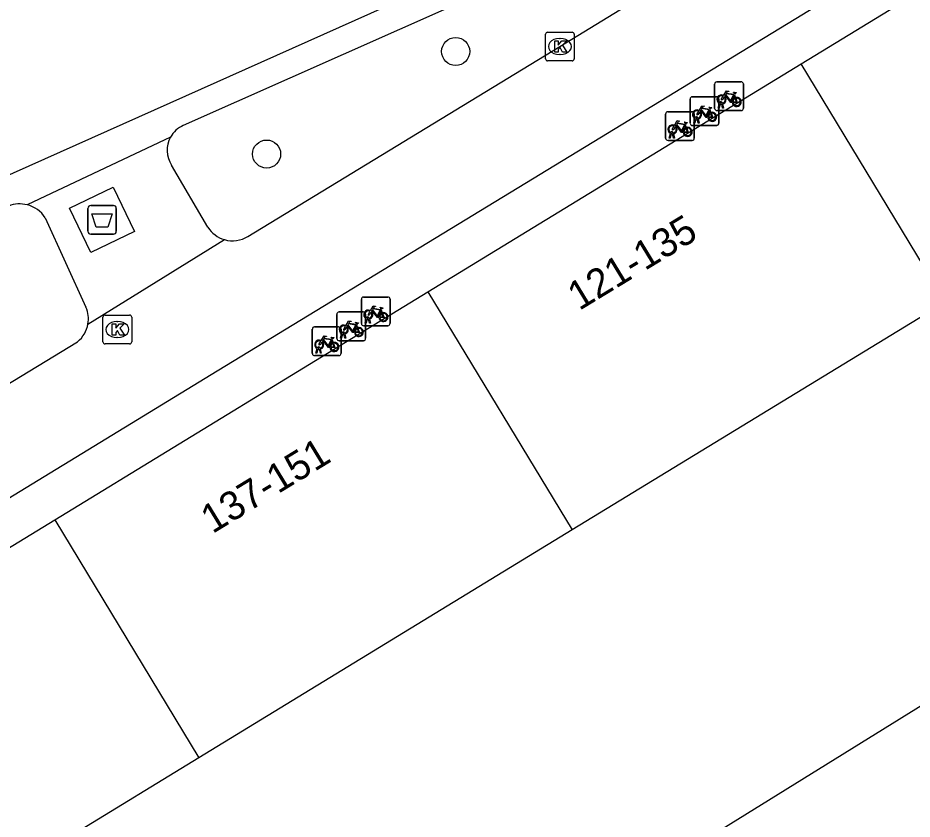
# Model space of a CAD drawing. Extents: x 159888 to 160757, y 384031 to 384746.
# Drawn here: x 160130.45 to 160161.59, y 384604.42 to 384632.33 of the extents above; entities that cross this region are included whole.
import ezdxf

# ---------------------------------------------------------------- set-up
doc = ezdxf.new("R2010")
doc.units = 0
for name, color, linetype in [('IMGEO_Afval_apart_plaats', 7, 'Continuous'), ('IMGEO_Boom', 7, 'Continuous'), ('IMGEO_Fietsenrek', 7, 'Continuous'), ('IMGEO_Groenvoorziening', 7, 'Continuous'), ('IMGEO_Kolk', 7, 'Continuous'), ('IMGEO_Pand', 7, 'Continuous'), ('IMGEO_Pand_nummerreeks', 7, 'Continuous'), ('IMGEO_Rijbaan_lokaal_open', 7, 'Continuous'), ('IMGEO_Voetpad_gesloten', 7, 'Continuous'), ('IMGEO_Voetpad_open', 7, 'Continuous')]:
    doc.layers.add(name, color=color, linetype=linetype)

msp = doc.modelspace()

# ---------------------------------------------------------------- linework, layer by layer
at = {"layer": 'IMGEO_Afval_apart_plaats'}
for p, q in [((160132.989, 384625.793), (160133.779, 384625.793)), ((160133.779, 384625.793), (160132.989, 384625.793)), ((160132.889, 384624.893), (160132.889, 384625.693)), ((160132.889, 384625.693), (160132.889, 384624.893)), ((160133.879, 384625.693), (160133.879, 384624.893)), ((160133.879, 384624.893), (160133.879, 384625.693)), ((160133.779, 384624.793), (160132.989, 384624.793)), ((160132.989, 384624.793), (160133.779, 384624.793))]:
    msp.add_line(p, q, dxfattribs=at)
msp.add_lwpolyline([(160133.032, 384625.507), (160133.736, 384625.507), (160133.587, 384625.037), (160133.181, 384625.037), (160133.032, 384625.507)], dxfattribs=at)
for centre, start, end in [((160132.989, 384625.693), 90, 180), ((160132.989, 384625.693), 90, 180), ((160133.779, 384625.693), 0, 90), ((160133.779, 384625.693), 360, 90), ((160132.989, 384624.893), 180, 270), ((160132.989, 384624.893), 180, 270), ((160133.779, 384624.893), 270, 0), ((160133.779, 384624.893), 270, 0)]:
    msp.add_arc(centre, 0.1, start, end, dxfattribs=at)
at = {"layer": 'IMGEO_Boom'}
for centre in [(160145.695, 384631.156), (160139.113, 384627.584)]:
    msp.add_circle(centre, 0.489, dxfattribs=at)
at = {"layer": 'IMGEO_Fietsenrek'}
for p, q in [((160154.713, 384629.174), (160154.713, 384630.015)), ((160154.713, 384630.015), (160154.713, 384629.174)), ((160154.788, 384630.099), (160155.629, 384630.099)), ((160155.629, 384630.099), (160154.788, 384630.099)), ((160155.713, 384630.024), (160155.713, 384629.183)), ((160155.713, 384629.183), (160155.713, 384630.024)), ((160153.934, 384629.579), (160154.775, 384629.579)), ((160154.775, 384629.579), (160153.934, 384629.579)), ((160154.859, 384629.504), (160154.859, 384628.663)), ((160154.859, 384628.663), (160154.859, 384629.504)), ((160155.4, 384629.648), (160155.436, 384629.553)), ((160153.859, 384628.654), (160153.859, 384629.495)), ((160153.859, 384629.495), (160153.859, 384628.654)), ((160154.84, 384629.183), (160154.879, 384629.343)), ((160154.909, 384629.331), (160154.874, 384629.183)), ((160154.951, 384629.355), (160154.95, 384629.359)), ((160154.992, 384629.183), (160154.958, 384629.325)), ((160154.982, 384629.366), (160154.983, 384629.359)), ((160154.99, 384629.329), (160155.025, 384629.183)), ((160153.005, 384628.133), (160153.005, 384628.974)), ((160153.005, 384628.974), (160153.005, 384628.133)), ((160153.08, 384629.058), (160153.921, 384629.058)), ((160153.921, 384629.058), (160153.08, 384629.058)), ((160154.005, 384628.983), (160154.005, 384628.142)), ((160154.005, 384628.142), (160154.005, 384628.983)), ((160154.546, 384629.128), (160154.582, 384629.033)), ((160155.638, 384629.099), (160154.797, 384629.099)), ((160154.797, 384629.099), (160155.638, 384629.099)), ((160154.874, 384629.183), (160154.84, 384629.183)), ((160155.025, 384629.183), (160154.992, 384629.183)), ((160153.692, 384628.607), (160153.728, 384628.512)), ((160154.784, 384628.579), (160153.943, 384628.579)), ((160153.943, 384628.579), (160154.784, 384628.579)), ((160153.986, 384628.663), (160154.025, 384628.823)), ((160154.02, 384628.663), (160153.986, 384628.663)), ((160154.055, 384628.811), (160154.02, 384628.663)), ((160154.097, 384628.835), (160154.096, 384628.839)), ((160154.138, 384628.663), (160154.104, 384628.805)), ((160154.128, 384628.846), (160154.129, 384628.839)), ((160154.136, 384628.809), (160154.171, 384628.663)), ((160154.171, 384628.663), (160154.138, 384628.663)), ((160153.132, 384628.142), (160153.171, 384628.302)), ((160153.201, 384628.29), (160153.166, 384628.142)), ((160153.243, 384628.314), (160153.242, 384628.318)), ((160153.284, 384628.142), (160153.25, 384628.284)), ((160153.274, 384628.325), (160153.275, 384628.318)), ((160153.282, 384628.288), (160153.317, 384628.142)), ((160153.93, 384628.058), (160153.089, 384628.058)), ((160153.089, 384628.058), (160153.93, 384628.058)), ((160153.166, 384628.142), (160153.132, 384628.142)), ((160153.317, 384628.142), (160153.284, 384628.142)), ((160142.413, 384621.68), (160142.413, 384622.521)), ((160142.413, 384622.521), (160142.413, 384621.68)), ((160142.488, 384622.605), (160143.329, 384622.605)), ((160143.329, 384622.605), (160142.488, 384622.605)), ((160143.413, 384622.53), (160143.413, 384621.689)), ((160143.413, 384621.689), (160143.413, 384622.53)), ((160141.634, 384622.084), (160142.475, 384622.084)), ((160142.475, 384622.084), (160141.634, 384622.084)), ((160143.1, 384622.154), (160143.136, 384622.059)), ((160141.559, 384621.159), (160141.559, 384622)), ((160141.559, 384622), (160141.559, 384621.159)), ((160142.54, 384621.689), (160142.579, 384621.849)), ((160142.559, 384622.009), (160142.559, 384621.168)), ((160142.559, 384621.168), (160142.559, 384622.009)), ((160142.609, 384621.837), (160142.574, 384621.689)), ((160142.651, 384621.861), (160142.65, 384621.865)), ((160142.692, 384621.689), (160142.658, 384621.831)), ((160142.682, 384621.872), (160142.683, 384621.865)), ((160142.69, 384621.835), (160142.725, 384621.689)), ((160140.705, 384620.639), (160140.705, 384621.48)), ((160140.705, 384621.48), (160140.705, 384620.639)), ((160140.78, 384621.564), (160141.621, 384621.564)), ((160141.621, 384621.564), (160140.78, 384621.564)), ((160141.705, 384621.489), (160141.705, 384620.648)), ((160141.705, 384620.648), (160141.705, 384621.489)), ((160142.246, 384621.633), (160142.282, 384621.538)), ((160143.338, 384621.605), (160142.497, 384621.605)), ((160142.497, 384621.605), (160143.338, 384621.605)), ((160142.574, 384621.689), (160142.54, 384621.689)), ((160142.725, 384621.689), (160142.692, 384621.689)), ((160141.392, 384621.113), (160141.428, 384621.018)), ((160141.686, 384621.168), (160141.725, 384621.328)), ((160141.72, 384621.168), (160141.686, 384621.168)), ((160141.755, 384621.316), (160141.72, 384621.168)), ((160141.797, 384621.34), (160141.796, 384621.344)), ((160141.838, 384621.168), (160141.804, 384621.31)), ((160141.828, 384621.351), (160141.829, 384621.344)), ((160141.836, 384621.314), (160141.871, 384621.168)), ((160141.871, 384621.168), (160141.838, 384621.168)), ((160140.832, 384620.648), (160140.871, 384620.808)), ((160140.901, 384620.796), (160140.866, 384620.648)), ((160140.943, 384620.82), (160140.942, 384620.824)), ((160140.984, 384620.648), (160140.95, 384620.79)), ((160140.974, 384620.831), (160140.975, 384620.824)), ((160140.982, 384620.794), (160141.017, 384620.648)), ((160142.484, 384621.084), (160141.643, 384621.084)), ((160141.643, 384621.084), (160142.484, 384621.084)), ((160141.63, 384620.564), (160140.789, 384620.564)), ((160140.789, 384620.564), (160141.63, 384620.564)), ((160140.866, 384620.648), (160140.832, 384620.648)), ((160141.017, 384620.648), (160140.984, 384620.648))]:
    msp.add_line(p, q, dxfattribs=at)
for points in [[(160155.047, 384629.573), (160154.995, 384629.483), (160154.955, 384629.458), (160154.956, 384629.505), (160155.011, 384629.599)], [(160155.026, 384629.625), (160155.121, 384629.789), (160155.207, 384629.775), (160155.209, 384629.766), (160155.153, 384629.755), (160155.126, 384629.71), (160155.382, 384629.669)], [(160155.322, 384629.381), (160155.272, 384629.381), (160155.081, 384629.632), (160155.062, 384629.6)], [(160155.369, 384629.644), (160155.112, 384629.685), (160155.095, 384629.656), (160155.262, 384629.436), (160155.369, 384629.644)], [(160155.417, 384629.546), (160155.387, 384629.623), (160155.278, 384629.405), (160155.321, 384629.405)], [(160155.351, 384629.405), (160155.471, 384629.404), (160155.427, 384629.518)], [(160155.447, 384629.525), (160155.502, 384629.38), (160155.352, 384629.38)], [(160155.382, 384629.669), (160155.407, 384629.718), (160155.401, 384629.722), (160155.378, 384629.726), (160155.366, 384629.733), (160155.365, 384629.736), (160155.367, 384629.741), (160155.462, 384629.726), (160155.464, 384629.716), (160155.454, 384629.703), (160155.442, 384629.697), (160155.428, 384629.703), (160155.4, 384629.648)], [(160154.172, 384629.105), (160154.267, 384629.269), (160154.353, 384629.255), (160154.355, 384629.246), (160154.299, 384629.235), (160154.272, 384629.19), (160154.528, 384629.149)], [(160154.528, 384629.149), (160154.553, 384629.198), (160154.547, 384629.202), (160154.524, 384629.206), (160154.512, 384629.213), (160154.511, 384629.216), (160154.513, 384629.221), (160154.608, 384629.206), (160154.61, 384629.196), (160154.6, 384629.183), (160154.588, 384629.177), (160154.574, 384629.183), (160154.546, 384629.128)], [(160154.193, 384629.053), (160154.141, 384628.963), (160154.101, 384628.938), (160154.102, 384628.985), (160154.157, 384629.079)], [(160154.468, 384628.861), (160154.418, 384628.861), (160154.227, 384629.112), (160154.208, 384629.08)], [(160154.515, 384629.124), (160154.258, 384629.165), (160154.241, 384629.136), (160154.408, 384628.916), (160154.515, 384629.124)], [(160154.563, 384629.026), (160154.533, 384629.103), (160154.424, 384628.885), (160154.467, 384628.885)], [(160154.497, 384628.885), (160154.617, 384628.884), (160154.573, 384628.998)], [(160154.593, 384629.005), (160154.648, 384628.86), (160154.498, 384628.86)], [(160153.318, 384628.584), (160153.413, 384628.748), (160153.499, 384628.734), (160153.501, 384628.725), (160153.445, 384628.714), (160153.418, 384628.669), (160153.674, 384628.628)], [(160153.614, 384628.34), (160153.564, 384628.34), (160153.373, 384628.591), (160153.354, 384628.559)], [(160153.661, 384628.603), (160153.404, 384628.644), (160153.387, 384628.615), (160153.554, 384628.395), (160153.661, 384628.603)], [(160153.709, 384628.505), (160153.679, 384628.582), (160153.57, 384628.364), (160153.613, 384628.364)], [(160153.674, 384628.628), (160153.699, 384628.677), (160153.693, 384628.681), (160153.67, 384628.685), (160153.658, 384628.692), (160153.657, 384628.695), (160153.659, 384628.7), (160153.754, 384628.685), (160153.756, 384628.675), (160153.746, 384628.662), (160153.734, 384628.656), (160153.72, 384628.662), (160153.692, 384628.607)], [(160153.339, 384628.532), (160153.287, 384628.442), (160153.247, 384628.417), (160153.248, 384628.464), (160153.303, 384628.558)], [(160153.643, 384628.364), (160153.763, 384628.363), (160153.719, 384628.477)], [(160153.739, 384628.484), (160153.794, 384628.339), (160153.644, 384628.339)], [(160142.747, 384622.079), (160142.695, 384621.989), (160142.655, 384621.964), (160142.656, 384622.011), (160142.711, 384622.105)], [(160142.726, 384622.131), (160142.821, 384622.295), (160142.907, 384622.281), (160142.909, 384622.272), (160142.853, 384622.261), (160142.826, 384622.216), (160143.082, 384622.175)], [(160143.022, 384621.887), (160142.972, 384621.887), (160142.781, 384622.138), (160142.762, 384622.106)], [(160143.069, 384622.15), (160142.812, 384622.191), (160142.795, 384622.162), (160142.962, 384621.942), (160143.069, 384622.15)], [(160143.117, 384622.052), (160143.087, 384622.129), (160142.978, 384621.911), (160143.021, 384621.911)], [(160143.147, 384622.031), (160143.202, 384621.886), (160143.052, 384621.886)], [(160143.082, 384622.175), (160143.107, 384622.224), (160143.101, 384622.228), (160143.078, 384622.232), (160143.066, 384622.239), (160143.065, 384622.242), (160143.067, 384622.247), (160143.162, 384622.232), (160143.164, 384622.222), (160143.154, 384622.209), (160143.142, 384622.203), (160143.128, 384622.209), (160143.1, 384622.154)], [(160141.872, 384621.61), (160141.967, 384621.774), (160142.053, 384621.76), (160142.055, 384621.751), (160141.999, 384621.74), (160141.972, 384621.695), (160142.228, 384621.654)], [(160142.228, 384621.654), (160142.253, 384621.703), (160142.247, 384621.707), (160142.224, 384621.711), (160142.212, 384621.718), (160142.211, 384621.721), (160142.213, 384621.726), (160142.308, 384621.711), (160142.31, 384621.701), (160142.3, 384621.688), (160142.288, 384621.682), (160142.274, 384621.688), (160142.246, 384621.633)], [(160143.051, 384621.911), (160143.171, 384621.91), (160143.127, 384622.024)], [(160141.893, 384621.558), (160141.841, 384621.468), (160141.801, 384621.443), (160141.802, 384621.49), (160141.857, 384621.584)], [(160142.168, 384621.366), (160142.118, 384621.366), (160141.927, 384621.617), (160141.908, 384621.585)], [(160142.215, 384621.629), (160141.958, 384621.67), (160141.941, 384621.641), (160142.108, 384621.421), (160142.215, 384621.629)], [(160142.263, 384621.531), (160142.233, 384621.608), (160142.124, 384621.39), (160142.167, 384621.39)], [(160142.197, 384621.39), (160142.317, 384621.389), (160142.273, 384621.503)], [(160142.293, 384621.51), (160142.348, 384621.365), (160142.198, 384621.365)], [(160141.018, 384621.09), (160141.113, 384621.254), (160141.199, 384621.24), (160141.201, 384621.231), (160141.145, 384621.22), (160141.118, 384621.175), (160141.374, 384621.134)], [(160141.314, 384620.846), (160141.264, 384620.846), (160141.073, 384621.097), (160141.054, 384621.065)], [(160141.361, 384621.109), (160141.104, 384621.15), (160141.087, 384621.121), (160141.254, 384620.901), (160141.361, 384621.109)], [(160141.374, 384621.134), (160141.399, 384621.183), (160141.393, 384621.187), (160141.37, 384621.191), (160141.358, 384621.198), (160141.357, 384621.201), (160141.359, 384621.206), (160141.454, 384621.191), (160141.456, 384621.181), (160141.446, 384621.168), (160141.434, 384621.162), (160141.42, 384621.168), (160141.392, 384621.113)], [(160141.039, 384621.038), (160140.987, 384620.948), (160140.947, 384620.923), (160140.948, 384620.97), (160141.003, 384621.064)], [(160141.409, 384621.011), (160141.379, 384621.088), (160141.27, 384620.87), (160141.313, 384620.87)], [(160141.343, 384620.87), (160141.463, 384620.869), (160141.419, 384620.983)], [(160141.439, 384620.99), (160141.494, 384620.845), (160141.344, 384620.845)]]:
    msp.add_lwpolyline(points, dxfattribs=at)
for centre, radius, start, end in [((160154.791, 384630.021), 0.0779, 92.4484, 184.2845), ((160154.791, 384630.021), 0.0779, 92.4484, 184.2845), ((160155.635, 384630.021), 0.0779, 2.4484, 94.2845), ((160155.635, 384630.021), 0.0779, 2.4484, 94.2845), ((160153.937, 384629.501), 0.0779, 92.4484, 184.2845), ((160153.937, 384629.501), 0.0779, 92.4484, 184.2845), ((160154.781, 384629.501), 0.0779, 2.4484, 94.2845), ((160154.781, 384629.501), 0.0779, 2.4484, 94.2845), ((160154.953, 384629.484), 0.159, 62.6766, 242.1369), ((160154.953, 384629.484), 0.129, 63.3192, 238.903), ((160154.953, 384629.484), 0.129, 283.6043, 43.4302), ((160154.953, 384629.484), 0.159, 283.5766, 46.6042), ((160155.48, 384629.4), 0.159, 113.3408, 178.3217), ((160155.48, 384629.4), 0.159, 187.0065, 105.7708), ((160155.48, 384629.4), 0.129, 113.923, 177.9556), ((160155.48, 384629.4), 0.129, 188.6715, 104.5883), ((160154.933, 384629.355), 0.0499, 12.8025, 158.6934), ((160154.953, 384629.484), 0.159, 253.9967, 271.7867), ((160154.933, 384629.355), 0.0174, 12.8025, 163.4502), ((160154.953, 384629.484), 0.129, 253.415, 269.0204), ((160153.083, 384628.98), 0.0779, 92.4484, 184.2845), ((160153.083, 384628.98), 0.0779, 92.4484, 184.2845), ((160153.927, 384628.98), 0.0779, 2.4484, 94.2845), ((160153.927, 384628.98), 0.0779, 2.4484, 94.2845), ((160154.099, 384628.964), 0.159, 62.6766, 242.1369), ((160154.099, 384628.964), 0.129, 63.3192, 238.903), ((160154.079, 384628.835), 0.0499, 12.8025, 158.6934), ((160154.099, 384628.964), 0.129, 283.6043, 43.4302), ((160154.099, 384628.964), 0.159, 283.5766, 46.6042), ((160154.626, 384628.88), 0.159, 113.3408, 178.3217), ((160154.626, 384628.88), 0.159, 187.0065, 105.7708), ((160154.626, 384628.88), 0.129, 113.923, 177.9556), ((160154.626, 384628.88), 0.129, 188.6715, 104.5883), ((160154.791, 384629.177), 0.0779, 182.4484, 274.2845), ((160154.791, 384629.177), 0.0779, 182.4484, 274.2845), ((160155.635, 384629.177), 0.0779, 272.4484, 4.2845), ((160155.635, 384629.177), 0.0779, 272.4484, 4.2845), ((160153.245, 384628.443), 0.159, 62.6766, 242.1369), ((160153.245, 384628.443), 0.129, 63.3192, 238.903), ((160153.937, 384628.657), 0.0779, 182.4484, 274.2845), ((160153.937, 384628.657), 0.0779, 182.4484, 274.2845), ((160154.099, 384628.964), 0.159, 253.9967, 271.7867), ((160154.079, 384628.835), 0.0174, 12.8025, 163.4502), ((160154.099, 384628.964), 0.129, 253.415, 269.0204), ((160154.781, 384628.657), 0.0779, 272.4484, 4.2845), ((160154.781, 384628.657), 0.0779, 272.4484, 4.2845), ((160153.225, 384628.314), 0.0499, 12.8025, 158.6934), ((160153.245, 384628.443), 0.159, 253.9967, 271.7867), ((160153.225, 384628.314), 0.0174, 12.8025, 163.4502), ((160153.245, 384628.443), 0.129, 253.415, 269.0204), ((160153.245, 384628.443), 0.129, 283.6043, 43.4302), ((160153.245, 384628.443), 0.159, 283.5766, 46.6042), ((160153.772, 384628.359), 0.159, 113.3408, 178.3217), ((160153.772, 384628.359), 0.159, 187.0065, 105.7708), ((160153.772, 384628.359), 0.129, 113.923, 177.9556), ((160153.772, 384628.359), 0.129, 188.6715, 104.5883), ((160153.083, 384628.136), 0.0779, 182.4484, 274.2845), ((160153.083, 384628.136), 0.0779, 182.4484, 274.2845), ((160153.927, 384628.136), 0.0779, 272.4484, 4.2845), ((160153.927, 384628.136), 0.0779, 272.4484, 4.2845), ((160142.491, 384622.527), 0.0779, 92.4484, 184.2845), ((160142.491, 384622.527), 0.0779, 92.4484, 184.2845), ((160143.335, 384622.527), 0.0779, 2.4484, 94.2845), ((160143.335, 384622.527), 0.0779, 2.4484, 94.2845), ((160141.637, 384622.006), 0.0779, 92.4484, 184.2845), ((160141.637, 384622.006), 0.0779, 92.4484, 184.2845), ((160142.481, 384622.006), 0.0779, 2.4484, 94.2845), ((160142.481, 384622.006), 0.0779, 2.4484, 94.2845), ((160142.653, 384621.99), 0.159, 62.6766, 242.1369), ((160142.653, 384621.99), 0.129, 63.3192, 238.903), ((160142.653, 384621.99), 0.129, 283.6043, 43.4302), ((160142.653, 384621.99), 0.159, 283.5766, 46.6042), ((160143.18, 384621.906), 0.159, 113.3408, 178.3217), ((160143.18, 384621.906), 0.159, 187.0065, 105.7708), ((160143.18, 384621.906), 0.129, 188.6715, 104.5883), ((160142.633, 384621.861), 0.0499, 12.8025, 158.6934), ((160142.653, 384621.99), 0.159, 253.9967, 271.7867), ((160142.633, 384621.861), 0.0174, 12.8025, 163.4502), ((160142.653, 384621.99), 0.129, 253.415, 269.0204), ((160143.18, 384621.906), 0.129, 113.923, 177.9556), ((160140.783, 384621.486), 0.0779, 92.4484, 184.2845), ((160140.783, 384621.486), 0.0779, 92.4484, 184.2845), ((160141.627, 384621.486), 0.0779, 2.4484, 94.2845), ((160141.627, 384621.486), 0.0779, 2.4484, 94.2845), ((160141.799, 384621.469), 0.159, 62.6766, 242.1369), ((160141.799, 384621.469), 0.129, 63.3192, 238.903), ((160141.799, 384621.469), 0.129, 283.6043, 43.4302), ((160141.799, 384621.469), 0.159, 283.5766, 46.6042), ((160142.326, 384621.385), 0.159, 113.3408, 178.3217), ((160142.326, 384621.385), 0.159, 187.0065, 105.7708), ((160142.326, 384621.385), 0.129, 113.923, 177.9556), ((160142.326, 384621.385), 0.129, 188.6715, 104.5883), ((160142.491, 384621.683), 0.0779, 182.4484, 274.2845), ((160142.491, 384621.683), 0.0779, 182.4484, 274.2845), ((160143.335, 384621.683), 0.0779, 272.4484, 4.2845), ((160143.335, 384621.683), 0.0779, 272.4484, 4.2845), ((160140.945, 384620.949), 0.159, 62.6766, 242.1369), ((160141.637, 384621.162), 0.0779, 182.4484, 274.2845), ((160141.637, 384621.162), 0.0779, 182.4484, 274.2845), ((160141.779, 384621.34), 0.0499, 12.8025, 158.6934), ((160141.799, 384621.469), 0.159, 253.9967, 271.7867), ((160141.779, 384621.34), 0.0174, 12.8025, 163.4502), ((160141.799, 384621.469), 0.129, 253.415, 269.0204), ((160142.481, 384621.162), 0.0779, 272.4484, 4.2845), ((160142.481, 384621.162), 0.0779, 272.4484, 4.2845), ((160140.945, 384620.949), 0.129, 63.3192, 238.903), ((160140.925, 384620.82), 0.0499, 12.8025, 158.6934), ((160140.945, 384620.949), 0.159, 253.9967, 271.7867), ((160140.925, 384620.82), 0.0174, 12.8025, 163.4502), ((160140.945, 384620.949), 0.129, 253.415, 269.0204), ((160140.945, 384620.949), 0.129, 283.6043, 43.4302), ((160140.945, 384620.949), 0.159, 283.5766, 46.6042), ((160141.472, 384620.865), 0.159, 113.3408, 178.3217), ((160141.472, 384620.865), 0.159, 187.0065, 105.7708), ((160141.472, 384620.865), 0.129, 113.923, 177.9556), ((160141.472, 384620.865), 0.129, 188.6715, 104.5883), ((160140.783, 384620.642), 0.0779, 182.4484, 274.2845), ((160140.783, 384620.642), 0.0779, 182.4484, 274.2845), ((160141.627, 384620.642), 0.0779, 272.4484, 4.2845), ((160141.627, 384620.642), 0.0779, 272.4484, 4.2845)]:
    msp.add_arc(centre, radius, start, end, dxfattribs=at)
at = {"layer": 'IMGEO_Groenvoorziening'}
msp.add_lwpolyline([(160114.059, 384578.949), (160127.142, 384586.832), (160189.258, 384625.337)], dxfattribs=at)
at = {"layer": 'IMGEO_Kolk'}
for p, q in [((160148.823, 384630.902), (160148.823, 384631.754)), ((160148.898, 384631.828), (160149.75, 384631.828)), ((160149.824, 384631.754), (160149.824, 384630.902)), ((160149.311, 384631.608), (160149.336, 384631.608)), ((160149.75, 384630.828), (160148.898, 384630.828)), ((160149.334, 384631.048), (160149.309, 384631.048)), ((160133.415, 384621.048), (160133.415, 384621.9)), ((160133.49, 384621.974), (160134.342, 384621.974)), ((160133.903, 384621.754), (160133.928, 384621.754)), ((160134.416, 384621.9), (160134.416, 384621.048)), ((160133.926, 384621.194), (160133.901, 384621.194)), ((160134.342, 384620.974), (160133.49, 384620.974))]:
    msp.add_line(p, q, dxfattribs=at)
for points in [[(160148.823, 384630.902), (160148.823, 384631.754)], [(160148.898, 384631.828), (160149.75, 384631.828)], [(160149.824, 384631.754), (160149.824, 384630.902)], [(160149.144, 384631.528), (160149.267, 384631.528), (160149.267, 384631.377), (160149.397, 384631.528), (160149.561, 384631.528), (160149.415, 384631.377), (160149.568, 384631.128), (160149.416, 384631.128), (160149.331, 384631.292), (160149.267, 384631.225), (160149.267, 384631.128), (160149.144, 384631.128), (160149.144, 384631.528)], [(160149.75, 384630.828), (160148.898, 384630.828)], [(160133.415, 384621.048), (160133.415, 384621.9)], [(160133.49, 384621.974), (160134.342, 384621.974)], [(160134.416, 384621.9), (160134.416, 384621.048)], [(160133.736, 384621.674), (160133.859, 384621.674), (160133.859, 384621.523), (160133.989, 384621.674), (160134.153, 384621.674), (160134.007, 384621.523), (160134.16, 384621.274), (160134.008, 384621.274), (160133.923, 384621.438), (160133.859, 384621.371), (160133.859, 384621.274), (160133.736, 384621.274), (160133.736, 384621.674)], [(160134.342, 384620.974), (160133.49, 384620.974)]]:
    msp.add_lwpolyline(points, dxfattribs=at)
for centre, start, end in [((160148.9, 384631.752), 91.552, 178.448), ((160148.9, 384631.752), 91.552, 178.448), ((160149.748, 384631.752), 1.552, 88.448), ((160149.748, 384631.752), 1.552, 88.448), ((160148.9, 384630.904), 181.552, 268.448), ((160148.9, 384630.904), 181.552, 268.448), ((160149.748, 384630.904), 271.552, 358.448), ((160149.748, 384630.904), 271.552, 358.448), ((160133.492, 384621.898), 91.552, 178.448), ((160133.492, 384621.898), 91.552, 178.448), ((160134.34, 384621.898), 1.552, 88.448), ((160134.34, 384621.898), 1.552, 88.448), ((160133.492, 384621.05), 181.552, 268.448), ((160133.492, 384621.05), 181.552, 268.448), ((160134.34, 384621.05), 271.552, 358.448), ((160134.34, 384621.05), 271.552, 358.448)]:
    msp.add_arc(centre, 0.0765, start, end, dxfattribs=at)
for centre, major_axis, ratio, start_param, end_param in [((160149.31, 384631.328), (-0.387, 0.002), 0.722429, 4.712389, 7.853982), ((160149.335, 384631.328), (-0.39, 0.002), 0.717154, 1.570796, 4.712389), ((160133.902, 384621.474), (-0.387, 0.002), 0.722429, 4.712389, 7.853982), ((160133.927, 384621.474), (-0.39, 0.002), 0.717154, 1.570796, 4.712389)]:
    msp.add_ellipse(centre, major_axis=major_axis, ratio=ratio, start_param=start_param, end_param=end_param, dxfattribs=at)
at = {"layer": 'IMGEO_Pand'}
for points in [[(160157.726, 384630.724), (160170.722, 384638.665)], [(160144.73, 384622.782), (160157.726, 384630.724)], [(160162.752, 384622.431), (160157.726, 384630.724)], [(160131.734, 384614.841), (160144.73, 384622.782)], [(160144.73, 384622.782), (160149.754, 384614.494)], [(160162.752, 384622.431), (160149.754, 384614.494)], [(160118.738, 384606.9), (160131.734, 384614.841)], [(160131.734, 384614.841), (160136.756, 384606.556)], [(160149.754, 384614.494), (160136.756, 384606.556)], [(160136.756, 384606.556), (160123.758, 384598.618)]]:
    msp.add_lwpolyline(points, dxfattribs=at)
at = {"layer": 'IMGEO_Rijbaan_lokaal_open'}
msp.add_lwpolyline([(160178.864, 384648.558), (160178.178, 384648.254), (160165.367, 384642.524), (160146.544, 384634.198), (160128.638, 384626.191), (160112.569, 384619.039), (160093.773, 384610.631), (160093.382, 384610.454)], dxfattribs=at)
at = {"layer": 'IMGEO_Voetpad_gesloten'}
msp.add_lwpolyline([(160132.994, 384624.154), (160132.251, 384625.701), (160133.773, 384626.432), (160134.516, 384624.885), (160132.994, 384624.154)], dxfattribs=at)
at = {"layer": 'IMGEO_Voetpad_open'}
for points in [[(160183.001, 384647.819), (160137.178, 384619.898), (160101.924, 384598.362)], [(160160.559, 384639.402), (160136.213, 384628.578)], [(160138.459, 384624.717), (160149.323, 384631.329), (160160.968, 384638.453)], [(160135.768, 384628.17), (160130.775, 384625.816)], [(160137.068, 384625.036), (160135.8, 384627.202)], [(160131.406, 384625.367), (160132.822, 384622.247)], [(160132.891, 384621.663), (160137.645, 384624.604)], [(160096.731, 384599.212), (160100.758, 384601.692), (160116.343, 384611.201), (160132.533, 384621.049)]]:
    msp.add_lwpolyline(points, dxfattribs=at)
for centre, radius, start, end in [((160136.591, 384627.72), 0.938, 113.7391, 151.2934), ((160136.594, 384627.713), 0.944, 151.0352, 212.7516), ((160130.519, 384624.783), 1.064, 76.0845, 111.3783), ((160130.512, 384624.779), 1.07, 33.3521, 75.7789), ((160137.926, 384625.58), 1.016, 212.3918, 253.9638), ((160137.927, 384625.563), 1, 253.632, 302.1746), ((160131.875, 384621.839), 1.032, 350.177, 23.2996), ((160131.886, 384621.838), 1.02, 309.3624, 350.148)]:
    msp.add_arc(centre, radius, start, end, dxfattribs=at)

# ---------------------------------------------------------------- texts
at = {"layer": 'IMGEO_Pand_nummerreeks'}
for s, rotation, p in [('121-135', 31.354, (160149.996, 384622.114)), ('137-151', 31.3969, (160137.226, 384614.343))]:
    msp.add_text(s, height=1, rotation=rotation, dxfattribs=at).set_placement(p)

doc.saveas('drawing.dxf')
